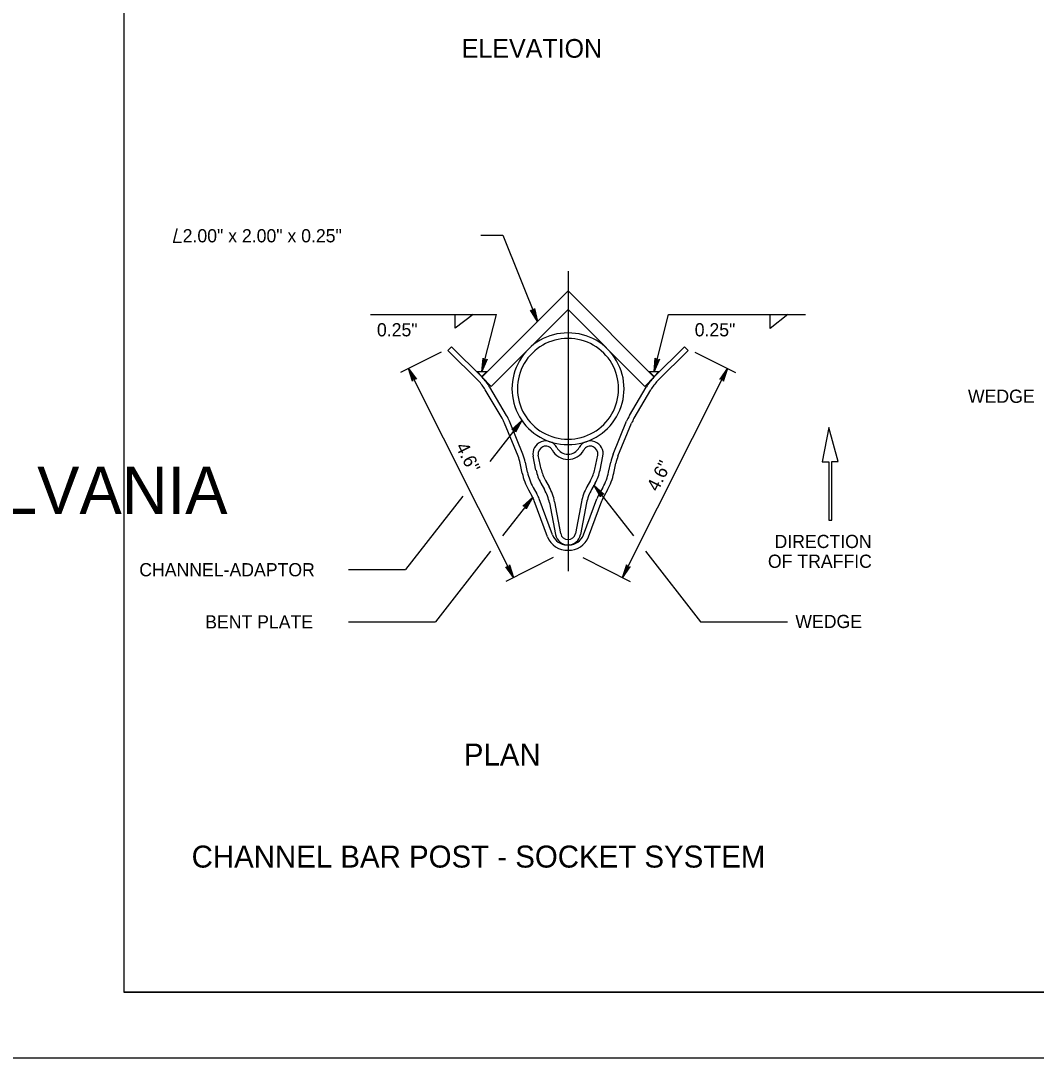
# Model space of a CAD drawing. Extents: x 644358 to 648627, y 294594 to 295782.
# Drawn here: x 646056.9 to 646287.7, y 294593.6 to 294829.5 of the extents above; entities that cross this region are included whole.
import ezdxf

# ---------------------------------------------------------------- set-up
doc = ezdxf.new("R2010")
doc.units = 0
for name, color, linetype in [('1', 7, 'Continuous'), ('2', 7, 'Continuous'), ('3', 7, 'Continuous'), ('4', 7, 'Continuous'), ('PLT-BNDY', 7, 'Continuous')]:
    doc.layers.add(name, color=color, linetype=linetype)

# ---------------------------------------------------------------- blocks, each defined once
blk = doc.blocks.new('RARROW')
at = {"layer": '3'}
blk.add_lwpolyline([(-2.2695, 0.285), (-2.184875, 0.12075), (0, 0), (-2.2695, 0.285), (-2.38575, 0.384625), (0, 0), (-2.183125, -0.108), (-2.262875, -0.2705), (0, 0), (-2.38575, -0.379125), (-2.262875, -0.2705)], dxfattribs=at)

msp = doc.modelspace()

# ---------------------------------------------------------------- linework, layer by layer
at = {"layer": '1'}
for p, q in [((646080.31, 295172.63), (646080.31, 294608.63)), ((646181.28, 294772.58), (646181.28, 294704.35)), ((646181.28, 294772.58), (646181.28, 294704.35)), ((646181.04, 294710.32), (646181.28, 294710.32)), ((646181.52, 294710.32), (646181.28, 294710.32)), ((646866.31, 294608.63), (646080.31, 294608.63)), ((646080.31, 294608.63), (646666.31, 294608.63))]:
    msp.add_line(p, q, dxfattribs=at)
at = {"layer": '2'}
for p, q in [((646093.41, 294779.05), (646091.56, 294779.05)), ((646161.43, 294780.71), (646166.43, 294780.71)), ((646166.43, 294780.71), (646174.34, 294761.12)), ((646136.39, 294762.67), (646165, 294762.67)), ((646155.65, 294759.56), (646155.65, 294762.67)), ((646159.71, 294762.67), (646155.65, 294759.56)), ((646161.71, 294749.73), (646165, 294762.67)), ((646200.85, 294749.73), (646204.13, 294762.67)), ((646204.13, 294762.67), (646235.29, 294762.67)), ((646227.19, 294759.55), (646227.19, 294762.67)), ((646231.26, 294762.67), (646227.19, 294759.55)), ((646152.45, 294754.17), (646143.23, 294749.54)), ((646210.11, 294754.17), (646219.33, 294749.54)), ((646168.91, 294702.91), (646145.02, 294750.44)), ((646193.65, 294702.91), (646217.54, 294750.44)), ((646160.62, 294749.73), (646162.81, 294749.73)), ((646161.71, 294748.63), (646160.62, 294749.73)), ((646162.81, 294749.73), (646161.71, 294748.63)), ((646199.75, 294749.73), (646201.94, 294749.73)), ((646200.85, 294748.63), (646199.75, 294749.73)), ((646201.94, 294749.73), (646200.85, 294748.63)), ((646170.79, 294738.59), (646163.51, 294729.26)), ((646240.56, 294737.03), (646239.08, 294729.22)), ((646242.67, 294729.3), (646240.56, 294737.03)), ((646239.08, 294729.22), (646240.53, 294729.22)), ((646240.53, 294729.22), (646240.53, 294715.98)), ((646241.23, 294715.98), (646241.23, 294729.3)), ((646241.23, 294729.3), (646242.67, 294729.3)), ((646187.18, 294723.9), (646196.17, 294712.38)), ((646157.39, 294721.42), (646144.35, 294704.71)), ((646173.25, 294721.17), (646166.39, 294712.38)), ((646240.53, 294715.98), (646241.23, 294715.98)), ((646163.66, 294708.89), (646151.16, 294692.87)), ((646198.9, 294708.89), (646211.4, 294692.87)), ((646177.92, 294707.44), (646167.12, 294702.01)), ((646184.64, 294707.44), (646195.44, 294702.01)), ((646131.41, 294704.71), (646144.35, 294704.71)), ((646131.41, 294692.87), (646151.16, 294692.87)), ((646211.4, 294692.87), (646231.15, 294692.87))]:
    msp.add_line(p, q, dxfattribs=at)
for centre, radius, start, end in [((646203.86, 294734.64), 10, 149.5025, 157.6977), ((646203.86, 294734.64), 8.8, 149.5025, 157.6977), ((646167.23, 294717.99), 6.8, 20.3297, 29.5668)]:
    msp.add_arc(centre, radius, start, end, dxfattribs=at)
at = {"layer": '3'}
for p, q in [((646161.71, 294748.49), (646181.28, 294768.06)), ((646200.85, 294748.49), (646181.28, 294768.06)), ((646163.83, 294746.37), (646181.28, 294763.82)), ((646198.73, 294746.37), (646181.28, 294763.82)), ((646154.83, 294755.37), (646153.99, 294754.52)), ((646161.77, 294748.44), (646154.83, 294755.37)), ((646200.79, 294748.44), (646207.73, 294755.37)), ((646207.73, 294755.37), (646208.57, 294754.52)), ((646160.92, 294747.59), (646153.99, 294754.52)), ((646201.64, 294747.59), (646208.57, 294754.52)), ((646163.83, 294746.37), (646161.77, 294748.44)), ((646198.73, 294746.37), (646200.79, 294748.44)), ((646172.04, 294726.89), (646171.58, 294729.15)), ((646174, 294727.3), (646173.35, 294730.47)), ((646175.18, 294727.54), (646174.52, 294730.71)), ((646187.38, 294727.54), (646188.04, 294730.71)), ((646188.56, 294727.3), (646189.21, 294730.47)), ((646190.52, 294726.89), (646190.98, 294729.15)), ((646170.87, 294726.65), (646170.4, 294728.91)), ((646191.69, 294726.65), (646192.16, 294728.91)), ((646175.1, 294724.39), (646175.93, 294722.93)), ((646176.14, 294724.98), (646176.97, 294723.52)), ((646186.42, 294724.98), (646185.59, 294723.52)), ((646187.46, 294724.39), (646186.63, 294722.93)), ((646172.31, 294722.81), (646173.14, 294721.35)), ((646173.36, 294723.4), (646174.19, 294721.94)), ((646189.2, 294723.4), (646188.37, 294721.94)), ((646190.25, 294722.81), (646189.42, 294721.35)), ((646176.63, 294712.19), (646173.61, 294720.36)), ((646177.76, 294712.61), (646174.73, 294720.77)), ((646177.05, 294719.88), (646178.43, 294712.68)), ((646178.23, 294720.1), (646179.61, 294712.9)), ((646184.33, 294720.1), (646182.95, 294712.9)), ((646185.51, 294719.88), (646184.13, 294712.68)), ((646184.8, 294712.61), (646187.83, 294720.77)), ((646185.93, 294712.19), (646188.95, 294720.36))]:
    msp.add_line(p, q, dxfattribs=at)
for points in [[(646166.29, 294739.11), (646162.46, 294745.6)], [(646167.32, 294739.72), (646163.5, 294746.2)], [(646195.24, 294739.72), (646199.06, 294746.2)], [(646196.28, 294739.11), (646200.1, 294745.6)], [(646169.93, 294730.47), (646166.84, 294737.98)], [(646171.04, 294730.92), (646167.95, 294738.44)], [(646191.52, 294730.92), (646194.61, 294738.44)], [(646192.63, 294730.47), (646195.72, 294737.98)]]:
    msp.add_lwpolyline(points, dxfattribs=at)
for centre, radius, start, end in [((646181.24, 294745.82), 12.7, 89.8201, 270.1799), ((646181.32, 294745.82), 12.7, 269.8201, 90.1799), ((646181.24, 294745.82), 11.45, 89.8005, 270.1995), ((646181.32, 294745.82), 11.45, 269.8005, 90.1995), ((646153.85, 294740.52), 11.2, 30.4975, 45), ((646208.71, 294740.52), 11.2, 135, 149.5025), ((646153.85, 294740.52), 10, 30.4975, 45), ((646208.71, 294740.52), 10, 135, 149.5025), ((646158.7, 294734.64), 8.8, 22.3023, 30.4975), ((646158.7, 294734.64), 10, 22.3023, 30.4975), ((646176.19, 294731.06), 2.9, 29.3625, 191.685), ((646186.37, 294731.06), 2.9, 348.315, 150.6375), ((646176.19, 294731.06), 1.7, 29.3625, 191.685), ((646181.27, 294733.85), 4.1, 208.2172, 270.2227), ((646181.27, 294733.85), 2.9, 208.2172, 270.2227), ((646181.29, 294733.85), 2.9, 269.7773, 331.7828), ((646181.29, 294733.85), 4.1, 269.7773, 331.7828), ((646186.37, 294731.06), 1.7, 348.315, 150.6375), ((646161.78, 294727.13), 8.8, 11.6854, 22.3023), ((646161.78, 294727.13), 10, 11.6854, 22.3023), ((646200.78, 294727.13), 10, 157.6977, 168.3146), ((646200.78, 294727.13), 8.8, 157.6977, 168.3146), ((646183.8, 294729.32), 12, 191.6854, 209.5668), ((646183.8, 294729.32), 10, 191.6854, 209.5668), ((646183.8, 294729.32), 8.8, 191.6854, 209.5668), ((646178.76, 294729.32), 8.8, 330.4332, 348.3146), ((646178.76, 294729.32), 10, 330.4332, 348.3146), ((646178.76, 294729.32), 12, 330.4332, 348.3146), ((646183.8, 294729.32), 13.2, 191.6854, 209.5668), ((646178.76, 294729.32), 13.2, 330.4332, 348.3146), ((646167.23, 294717.99), 8, 20.3297, 29.5668), ((646167.23, 294717.99), 10, 10.8647, 29.5668), ((646167.23, 294717.99), 11.2, 10.8647, 29.5668), ((646195.33, 294717.99), 11.2, 150.4332, 169.1353), ((646195.33, 294717.99), 10, 150.4332, 169.1353), ((646195.33, 294717.99), 8, 150.4332, 159.6703), ((646195.33, 294717.99), 6.8, 150.4332, 159.6703), ((646181.04, 294713.82), 3.5, 200.3297, 270), ((646181.28, 294713.22), 2.9, 190.8647, 270), ((646181.28, 294713.22), 1.7, 190.8647, 270), ((646181.28, 294713.22), 1.7, 270, 349.1353), ((646181.28, 294713.22), 2.9, 270, 349.1353), ((646181.52, 294713.82), 3.5, 270, 339.6703), ((646181.04, 294713.82), 4.7, 200.3297, 272.9539), ((646181.52, 294713.82), 4.7, 267.0461, 339.6703)]:
    msp.add_arc(centre, radius, start, end, dxfattribs=at)
at = {"layer": 'PLT-BNDY'}
msp.add_lwpolyline([(646040.31, 295187.63), (646881.31, 295187.63), (646881.31, 294593.63), (646040.31, 294593.63)], close=True, dxfattribs=at)

# ---------------------------------------------------------------- block references
at = {"layer": '2'}
for p, xscale, yscale, rotation in [((646174.34, 294761.12), 1.2574347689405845, 1.3092961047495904, -67.59902542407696), ((646161.71, 294749.73), 1.2574347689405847, 1.3092961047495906, -104.19570215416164), ((646200.85, 294749.73), 1.2574347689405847, 1.3092961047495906, -104.19570215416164), ((646145.02, 294750.44), 1.2574347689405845, 1.3092961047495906, 116.56916879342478), ((646217.54, 294750.44), 1.2574347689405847, -1.3092961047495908, 63.43083120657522), ((646170.79, 294738.59), 1.2574347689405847, 1.3092961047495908, 51.43561221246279), ((646187.18, 294723.9), 1.2574347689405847, 1.3092961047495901, 128.03213898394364), ((646173.25, 294721.17), 1.2574347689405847, 1.3092961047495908, 51.43561221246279), ((646168.91, 294702.91), 1.2574347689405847, 1.3092961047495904, -63.277657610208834), ((646193.65, 294702.91), 1.257434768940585, -1.3092961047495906, -116.7223423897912)]:
    msp.add_blockref('RARROW', p, dxfattribs=dict(at, xscale=xscale, yscale=yscale, rotation=rotation))

# ---------------------------------------------------------------- texts
at = {"layer": '1'}
msp.add_text('COMMONWEALTH OF PENNSYLVANIA', height=10.7828, dxfattribs=at).set_placement((645837.9, 294717.36))
at = {"layer": '2'}
for s, height, p in [('/ 2.00" x 2.00" x 0.25"', 3, (646091.47, 294779.1)), ('0.25"', 3, (646137.85, 294757.73)), ('0.25"', 3, (646210.08, 294757.73)), ('WEDGE', 3, (646272.18, 294742.62)), ('DIRECTION', 3, (646228.22, 294709.61)), ('OF TRAFFIC', 3, (646226.72, 294705.11)), ('CHANNEL-ADAPTOR', 3, (646083.83, 294703.18)), ('BENT PLATE', 3, (646098.81, 294691.32)), ('WEDGE', 3, (646232.95, 294691.42)), ('PLAN', 5, (646157.6, 294660.16)), ('CHANNEL BAR POST - SOCKET SYSTEM', 5, (646095.73, 294636.97))]:
    msp.add_text(s, height=height, dxfattribs=at).set_placement(p)
at = {"layer": '4'}
msp.add_text('ELEVATION', height=4.25, dxfattribs=at).set_placement((646157.13, 294821.07))
for rotation, p in [(296.6869, (646155.65, 294732.69)), (63.3131, (646201.69, 294722.25))]:
    msp.add_text('4.6"', height=3, rotation=rotation, dxfattribs=at).set_placement(p)

doc.saveas('drawing.dxf')
